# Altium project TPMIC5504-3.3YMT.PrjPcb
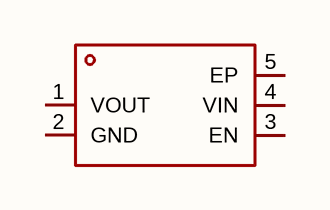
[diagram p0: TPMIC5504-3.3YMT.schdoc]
1 sheet, 1 parts. Net scope: global (net labels, ports and power ports of the same name join across sheets).

## Sheet TPMIC5504-3.3YMT.schdoc
size 127 x 101 mm

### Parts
U?  tpmic5504-3.3ymt  [DFN-4_L1.0-W1.0-P0.65-BL-EP-2]  (value not drawn)

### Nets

Not connected (* = marked no-connect by the designer): U? 1(VOUT) 2(GND) 3(EN) 4(VIN) 5(EP)

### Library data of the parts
U? = tpmic5504-3.3ymt: 输出极性:正极;工作电压:5.5V;输出电压:3.3V;输出电流:300mA;电源纹波抑制比(PSRR):-;输出类型:固定;; Manufacturer: TECH PUBLIC(台舟); AddInBom: yes; Output Configuration: 正极; Voltage - Supply: 5.5V; Output Voltage: 3.3V; Output Current: 300mA; Voltage Dropout: 180mV@(300mA); standby current: 15uA; Output Type: 固定; Number of Outputs: 1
